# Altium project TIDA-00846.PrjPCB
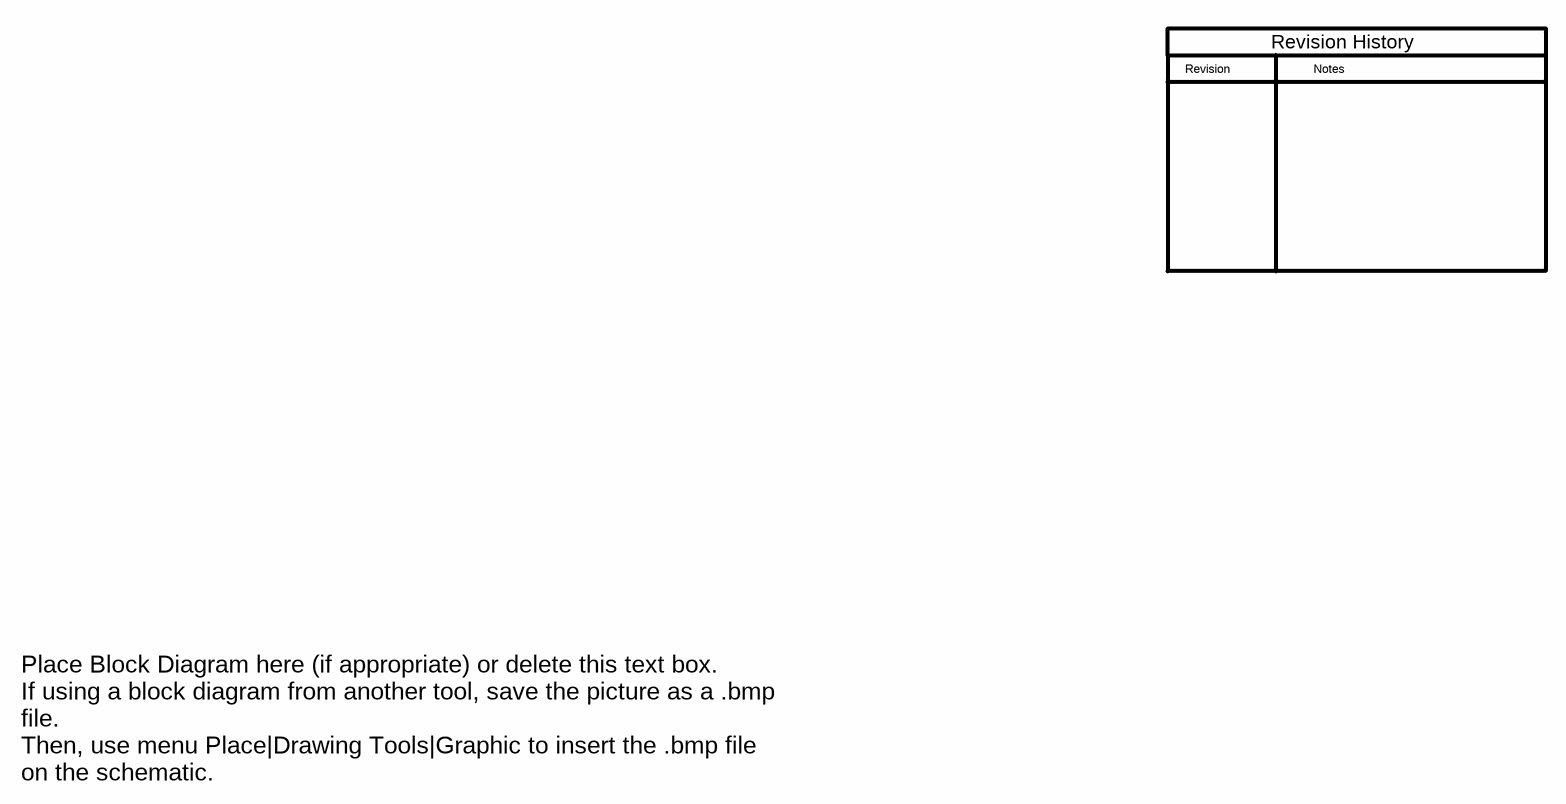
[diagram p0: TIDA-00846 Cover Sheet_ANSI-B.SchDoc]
CopyrightYear: 2015; PCB_Layout: Anda Zhang; PCB_Rev: E1; PRJ_Customer: Public Release; PRJ_Engineer: Anda Zhang; PRJ_Number: 001; PRJ_Title: TIDA-00846; SCH_Rev: E1; TechSupport: http://www.ti.com/support
3 sheets, 89 parts. Net scope: global (net labels, ports and power ports of the same name join across sheets).
Board file: TIDA-00846.PcbDoc
Sheets:
  TIDA-00846 Cover Sheet_ANSI-B.SchDoc
  TIDA-00846.SchDoc
  TIDA-00846_Hardware_ANSI-B.SchDoc

## Sheet TIDA-00846 Cover Sheet_ANSI-B.SchDoc
size 431 x 279 mm; Date: Not shown in title block; ApprovedBy: Not shown in title block; CheckedBy: Not shown in title block; Author: Not shown in title block; CompanyName: Not shown in title block; Engineer: Not shown in title block; Organization: Not shown in title block; Address1: Not shown in title block; Address2: Not shown in title block; Address3: Not shown in title block; Address4: Not shown in title block; DocumentNumber: 1; Revision: Use project parameter SCH_Rev; SheetNumber: 1; SheetTotal: 1; PageSetup: Record=PageOptions|CenterHorizontal=True|CenterVertical=True|PrintScale=1.00|XCorrection=1.00|YCorrection=1.00|PrintKind=0|BorderSize=5000000|LeftOffset=0|BottomOffset=0|Orientation=2|PaperLength=1000|PaperWidth=1000|Scale=100|PaperSource=15|PrintQuality=600|MediaType=1|DitherType=10|PaperKind=Letter|PrintScaleMode=1

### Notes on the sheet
- Revision
- Notes
- Revision History
- Place Block Diagram here (if appropriate) or delete this text box.
  If using a block diagram from another tool, save the picture as a .bmp file.
  Then, use menu Place|Drawing Tools|Graphic to insert the .bmp file on the schematic.

## Sheet TIDA-00846.SchDoc
size 558 x 431 mm; Date: Not shown in title block; ApprovedBy: Not shown in title block; CheckedBy: Not shown in title block; Author: Not shown in title block; CompanyName: Not shown in title block; Engineer: Not shown in title block; Organization: Not shown in title block; Address1: Not shown in title block; Address2: Not shown in title block; Address3: Not shown in title block; Address4: Not shown in title block; DocumentNumber: 1; Revision: Use project parameter SCH_Rev; SheetNumber: 1; SheetTotal: 1; PageSetup: Record=PageOptions¦CenterHorizontal=True¦CenterVertical=True¦PrintScale=1.00¦XCorrection=1.00¦YCorrection=1.00¦PrintKind=0¦BorderSize=5000000¦LeftOffset=0¦BottomOffset=0¦Orientation=2¦PaperLength=1000¦PaperWidth=1000¦Scale=100¦PaperSource=15¦PrintQuality=600¦MediaType=1¦DitherType=10¦PaperKind=Letter¦PrintScaleMode=1
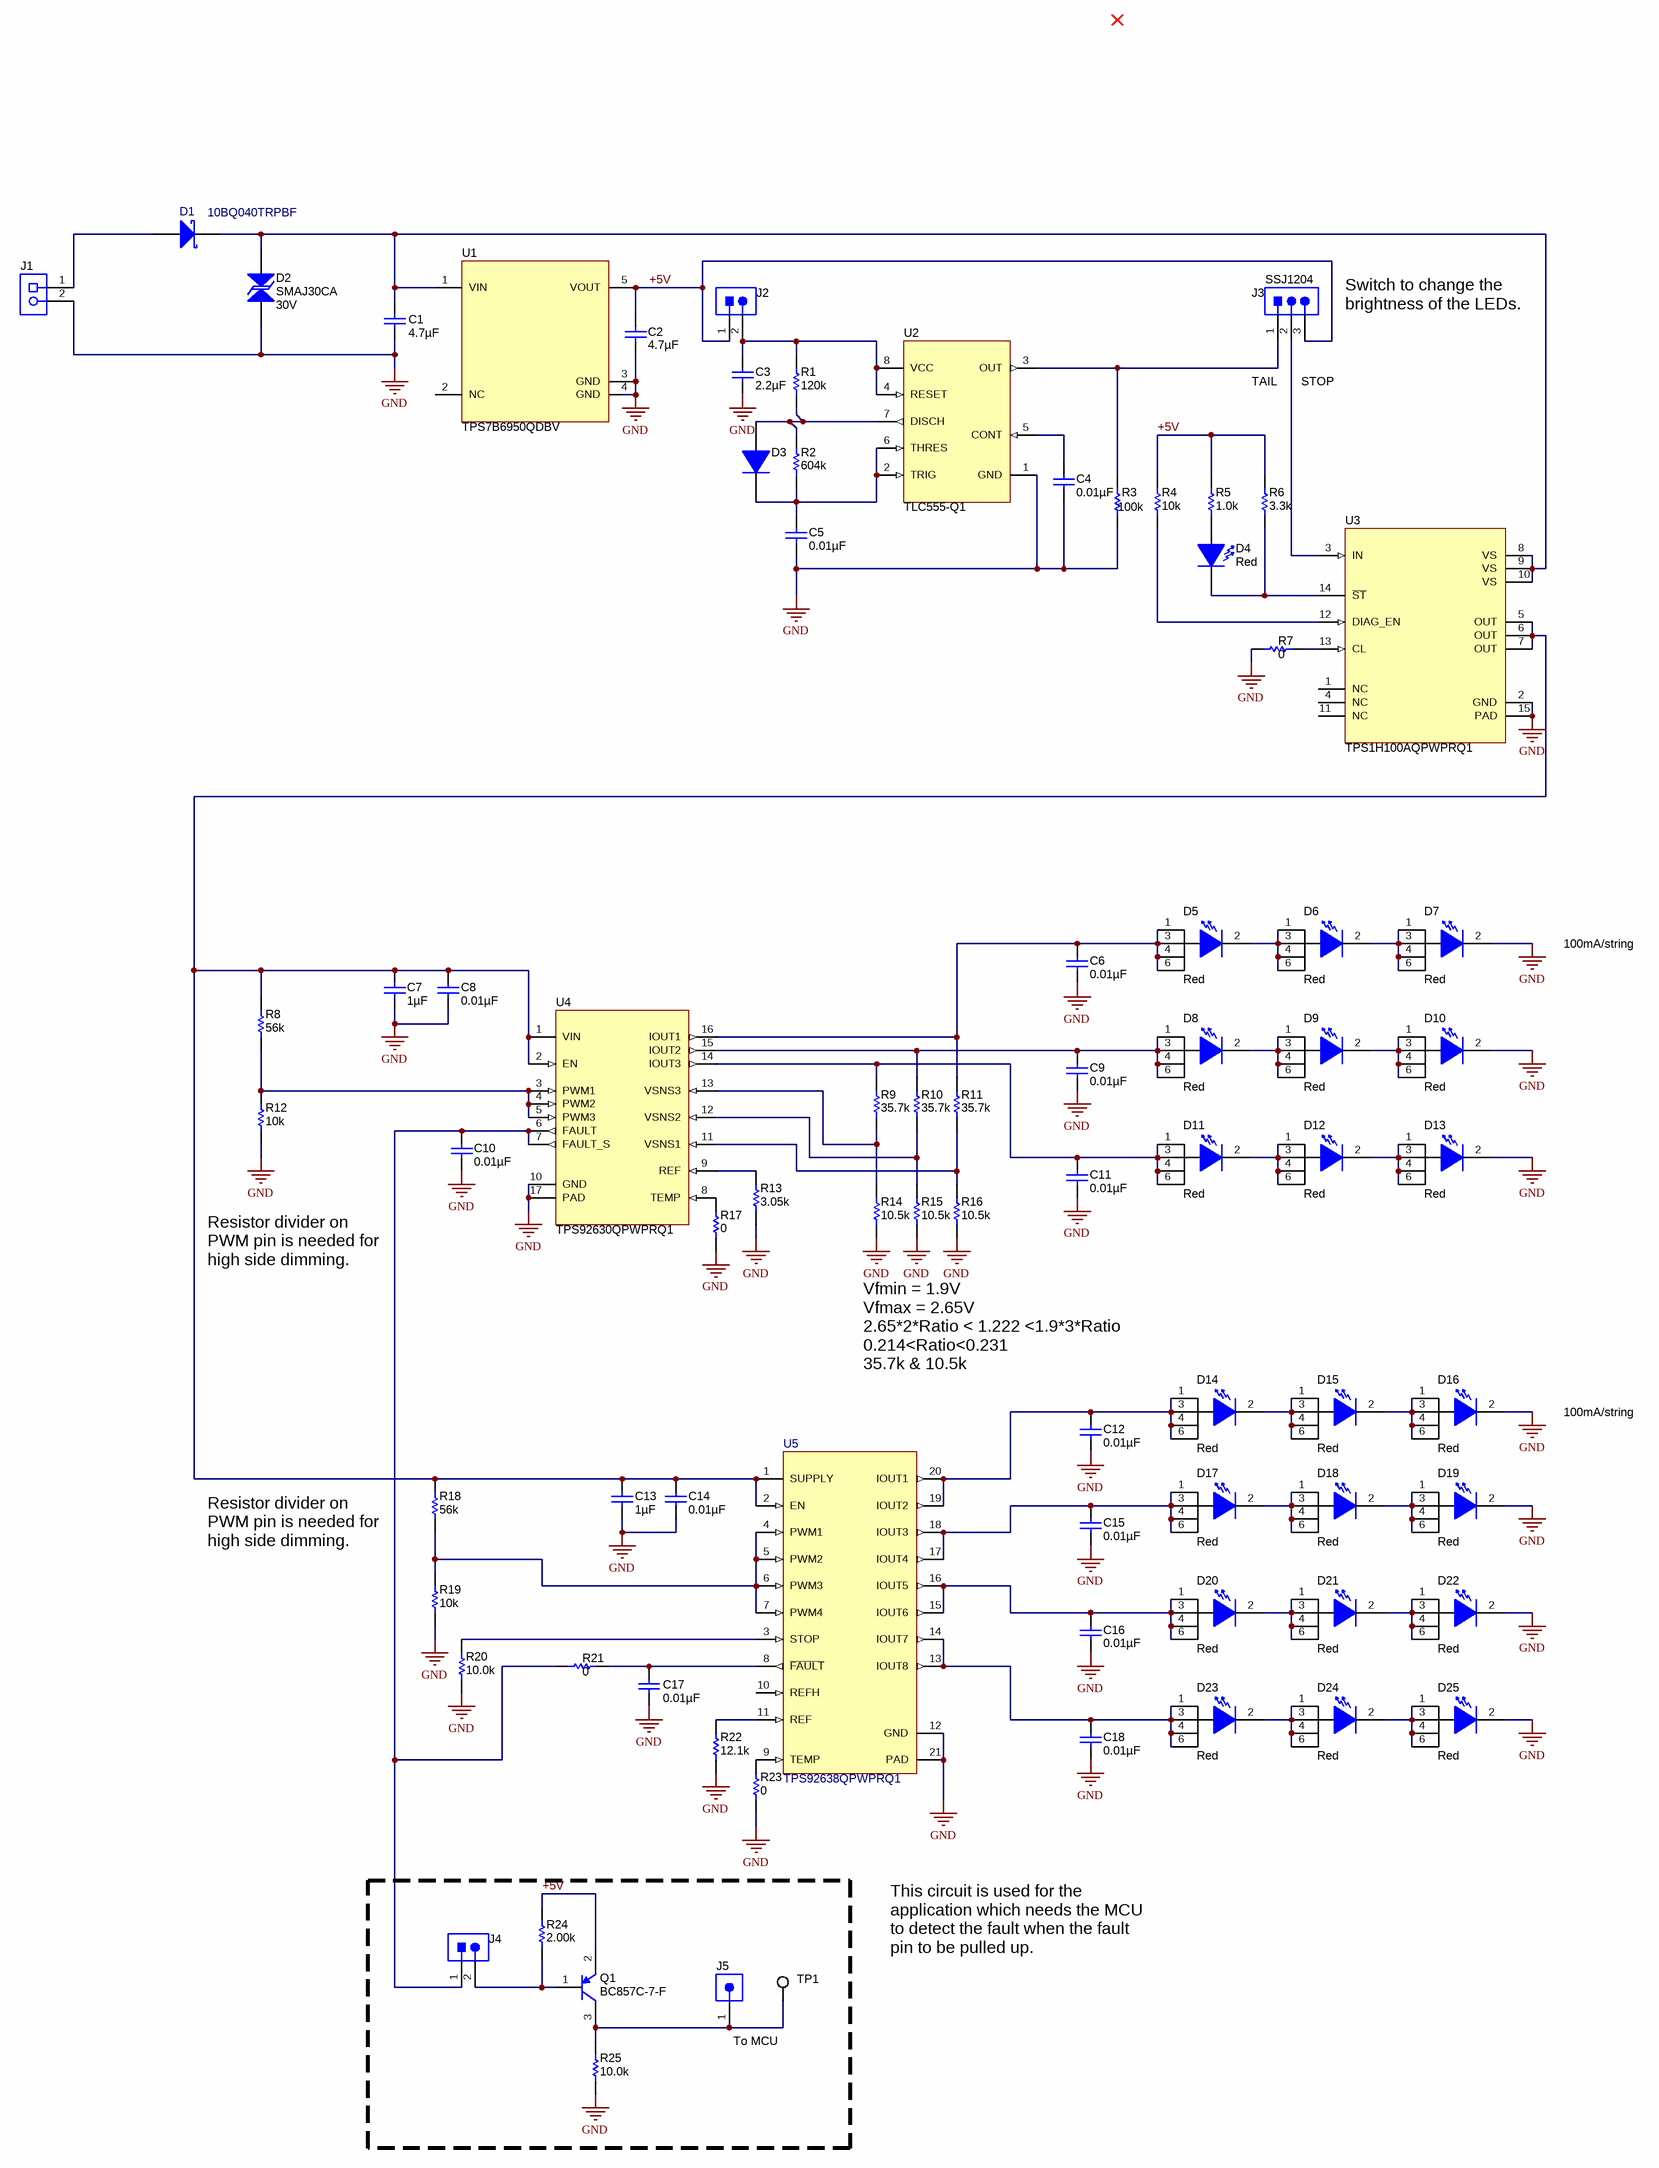
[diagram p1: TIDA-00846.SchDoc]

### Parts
C1  ValueDisplayed: 4.7µF  [0805L]  (hidden comment: C2012X5R1H475K125AB)
C2  ValueDisplayed: 4.7µF  [0603L]  (hidden comment: CGB3B1X5R1A475K055AC)
C3  ValueDisplayed: 2.2µF  [0603L]  (hidden comment: C0603C225K8PACTU)
C4  ValueDisplayed: 0.01µF  [0603L]  (hidden comment: 0603ZC103KAT2A)
C5  ValueDisplayed: 0.01µF  [0603L]  (hidden comment: 06031C103JAT2A)
C6  ValueDisplayed: 0.01µF  [0603L]  (hidden comment: 06031C103JAT2A)
C7  ValueDisplayed: 1µF  [0805L]  (hidden comment: C2012X7R1H105K125AB)
C8  ValueDisplayed: 0.01µF  [0603L]  (hidden comment: 06031C103JAT2A)
C9  ValueDisplayed: 0.01µF  [0603L]  (hidden comment: 06031C103JAT2A)
C10  ValueDisplayed: 0.01µF  [0603L]  (hidden comment: 06031C103JAT2A)
C11  ValueDisplayed: 0.01µF  [0603L]  (hidden comment: 06031C103JAT2A)
C12  ValueDisplayed: 0.01µF  [0603L]  (hidden comment: 06031C103JAT2A)
C13  ValueDisplayed: 1µF  [0805L]  (hidden comment: C2012X7R1H105K125AB)
C14  ValueDisplayed: 0.01µF  [0603L]  (hidden comment: 06031C103JAT2A)
C15  ValueDisplayed: 0.01µF  [0603L]  (hidden comment: 06031C103JAT2A)
C16  ValueDisplayed: 0.01µF  [0603L]  (hidden comment: 06031C103JAT2A)
C17  ValueDisplayed: 0.01µF  [0603L]  (hidden comment: 06031C103JAT2A)
C18  ValueDisplayed: 0.01µF  [0603L]  (hidden comment: 06031C103JAT2A)
D1  10BQ040TRPBF  [SMB]
D2  SMAJ30CA  value 30V  [SMA]
D3  1N4148W-7-F  [SOD-123]  (value not drawn)
D4  value Red  [LED_LTST-C170]  (hidden comment: LTST-C170KRKT)
D5  value Red  [LED_LR_G6SP]  (hidden comment: LR G6SP-CBEA-1-1)
D6  value Red  [LED_LR_G6SP]  (hidden comment: LR G6SP-CBEA-1-1)
D7  value Red  [LED_LR_G6SP]  (hidden comment: LR G6SP-CBEA-1-1)
D8  value Red  [LED_LR_G6SP]  (hidden comment: LR G6SP-CBEA-1-1)
D9  value Red  [LED_LR_G6SP]  (hidden comment: LR G6SP-CBEA-1-1)
D10  value Red  [LED_LR_G6SP]  (hidden comment: LR G6SP-CBEA-1-1)
D11  value Red  [LED_LR_G6SP]  (hidden comment: LR G6SP-CBEA-1-1)
D12  value Red  [LED_LR_G6SP]  (hidden comment: LR G6SP-CBEA-1-1)
D13  value Red  [LED_LR_G6SP]  (hidden comment: LR G6SP-CBEA-1-1)
D14  value Red  [LED_LR_G6SP]  (hidden comment: LR G6SP-CBEA-1-1)
D15  value Red  [LED_LR_G6SP]  (hidden comment: LR G6SP-CBEA-1-1)
D16  value Red  [LED_LR_G6SP]  (hidden comment: LR G6SP-CBEA-1-1)
D17  value Red  [LED_LR_G6SP]  (hidden comment: LR G6SP-CBEA-1-1)
D18  value Red  [LED_LR_G6SP]  (hidden comment: LR G6SP-CBEA-1-1)
D19  value Red  [LED_LR_G6SP]  (hidden comment: LR G6SP-CBEA-1-1)
D20  value Red  [LED_LR_G6SP]  (hidden comment: LR G6SP-CBEA-1-1)
D21  value Red  [LED_LR_G6SP]  (hidden comment: LR G6SP-CBEA-1-1)
D22  value Red  [LED_LR_G6SP]  (hidden comment: LR G6SP-CBEA-1-1)
D23  value Red  [LED_LR_G6SP]  (hidden comment: LR G6SP-CBEA-1-1)
D24  value Red  [LED_LR_G6SP]  (hidden comment: LR G6SP-CBEA-1-1)
D25  value Red  [LED_LR_G6SP]  (hidden comment: LR G6SP-CBEA-1-1)
J1  OSTTC022162  [On-Shore_OSTTC022162]  (value not drawn)
J2  HMTSW-102-07-G-S-240  [SAMTEC_HMTSW-102-07-G-S-240]  (value not drawn)
J3  value SSJ1204  [CONN_TMM-103-01-T-S]  (hidden comment: TMM-103-01-T-S)
J4  HMTSW-102-07-G-S-240  [SAMTEC_HMTSW-102-07-G-S-240]  (value not drawn)
J5  TSW-101-07-G-S  [TSW-101-07-G-S]  (value not drawn)
Q1  BC857C-7-F  [SOT-23]
R1  ValueDisplayed: 120k  [0603L]  (hidden comment: CRCW0603120KJNEA)
R2  ValueDisplayed: 604k  [0603]  (hidden comment: CRCW0603604KFKEA)
R3  ValueDisplayed: 100k  [0603L]  (hidden comment: CRCW0603100KFKEA)
R4  ValueDisplayed: 10k  [0603L]  (hidden comment: CRCW060310K0JNEA)
R5  ValueDisplayed: 1.0k  [0603L]  (hidden comment: CRCW06031K00JNEA)
R6  ValueDisplayed: 3.3k  [0603L]  (hidden comment: CRCW06033K30JNEA)
R7  ValueDisplayed: 0  [0603L]  (hidden comment: RC0603JR-070RL)
R8  ValueDisplayed: 56k  [0603L]  (hidden comment: CRCW060356K0JNEA)
R9  ValueDisplayed: 35.7k  [0603L]  (hidden comment: CRCW060335K7FKEA)
R10  ValueDisplayed: 35.7k  [0603L]  (hidden comment: CRCW060335K7FKEA)
R11  ValueDisplayed: 35.7k  [0603L]  (hidden comment: CRCW060335K7FKEA)
R12  ValueDisplayed: 10k  [0603L]  (hidden comment: CRCW060310K0JNEA)
R13  ValueDisplayed: 3.05k  [0603L]  (hidden comment: RT0603BRD073K05L)
R14  ValueDisplayed: 10.5k  [0603L]  (hidden comment: CRCW060310K5FKEA)
R15  ValueDisplayed: 10.5k  [0603L]  (hidden comment: CRCW060310K5FKEA)
R16  ValueDisplayed: 10.5k  [0603L]  (hidden comment: CRCW060310K5FKEA)
R17  ValueDisplayed: 0  [0603L]  (hidden comment: RC0603JR-070RL)
R18  ValueDisplayed: 56k  [0603L]  (hidden comment: CRCW060356K0JNEA)
R19  ValueDisplayed: 10k  [0603L]  (hidden comment: CRCW060310K0JNEA)
R20  ValueDisplayed: 10.0k  [0603L]  (hidden comment: CRCW060310K0FKEA)
R21  ValueDisplayed: 0  [0603L]  (hidden comment: RC0603JR-070RL)
R22  ValueDisplayed: 12.1k  [0603]  (hidden comment: RT0603DRE0712K1L)
R23  ValueDisplayed: 0  [0603L]  (hidden comment: RC0603JR-070RL)
R24  ValueDisplayed: 2.00k  [0603L]  (hidden comment: CRCW06032K00FKEA)
R25  ValueDisplayed: 10.0k  [0603L]  (hidden comment: CRCW060310K0FKEA)
TP1  5002  [Keystone5002]  (value not drawn)
U1  TPS7B6950QDBV  [DBV0005A_N]
U2  TLC555-Q1  [D0008A_L]
U3  TPS1H100AQPWPRQ1  [PWP0014C_N]
U4  TPS92630QPWPRQ1  [PWP0016F_N]
U5  TPS92638QPWPRQ1  [PWP0020B_N]

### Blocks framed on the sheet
To MCU: J4 J5 Q1 R24 R25 TP1

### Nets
GND: C1.2 C2.2 C3.2 C4.2 C5.2 C6.2 C7.2 C8.2 C9.2 C10.2 C11.2 C12.2 C13.2 C14.2 C15.2 C16.2 C17.2 C18.2 D2.1 D7.2(K) D10.2(K) D13.2(K) D16.2(K) D19.2(K) D22.2(K) D25.2(K) J1.2 R3.1 R7.2 R12.1 R13.1 R14.1 R15.1 R16.1 R17.1 R19.1 R20.1 R22.1 R23.1 R25.1 U1.3(GND) U1.4(GND) U2.1(GND) U3.2(GND) U3.15(PAD) U4.10(GND) U4.17(PAD) U5.12(GND) U5.21(PAD)
+5V: C2.1 J2.1 J3.3 Q1.2(E) R4.2 R5.2 R6.2 R24.2 U1.5(VOUT)
NetC1_1: C1.1 D1.1(K) D2.2 U1.1(VIN) U3.8(VS) U3.9(VS) U3.10(VS)
NetC3_1: C3.1 J2.2 R1.2 U2.4(RESET) U2.8(VCC)
NetC4_1: C4.1 U2.5(CONT)
NetC5_1: C5.1 D3.1(K) R2.1 U2.2(TRIG) U2.6(THRES)
NetC6_1: C6.1 D5.1(A) D5.3(A) D5.4(A) D5.6(A) R11.2 U4.16(IOUT1)
NetC7_1: C7.1 C8.1 C13.1 C14.1 R8.2 R18.2 U3.5(OUT) U3.6(OUT) U3.7(OUT) U4.1(VIN) U4.2(EN) U5.1(SUPPLY) U5.2(EN)
NetC9_1: C9.1 D8.1(A) D8.3(A) D8.4(A) D8.6(A) R10.2 U4.15(IOUT2)
NetC10_1: C10.1 J4.1 R21.2 U4.6(FAULT) U4.7(FAULT_S)
NetC11_1: C11.1 D11.1(A) D11.3(A) D11.4(A) D11.6(A) R9.2 U4.14(IOUT3)
NetC12_1: C12.1 D14.1(A) D14.3(A) D14.4(A) D14.6(A) U5.19(IOUT2) U5.20(IOUT1)
NetC15_1: C15.1 D17.1(A) D17.3(A) D17.4(A) D17.6(A) U5.17(IOUT4) U5.18(IOUT3)
NetC16_1: C16.1 D20.1(A) D20.3(A) D20.4(A) D20.6(A) U5.15(IOUT6) U5.16(IOUT5)
NetC17_1: C17.1 R21.1 U5.8(~{FAULT})
NetC18_1: C18.1 D23.1(A) D23.3(A) D23.4(A) D23.6(A) U5.13(IOUT8) U5.14(IOUT7)
NetD1_2: D1.2(A) J1.1
NetD3_2: D3.2(A) R1.1 R2.2 U2.7(DISCH)
NetD4_1: D4.1(A) R5.1
NetD4_2: D4.2(K) R6.1 U3.14(~{ST})
NetD5_2: D5.2(K) D6.1(A) D6.3(A) D6.4(A) D6.6(A)
NetD6_2: D6.2(K) D7.1(A) D7.3(A) D7.4(A) D7.6(A)
NetD8_2: D8.2(K) D9.1(A) D9.3(A) D9.4(A) D9.6(A)
NetD9_2: D9.2(K) D10.1(A) D10.3(A) D10.4(A) D10.6(A)
NetD11_2: D11.2(K) D12.1(A) D12.3(A) D12.4(A) D12.6(A)
NetD12_2: D12.2(K) D13.1(A) D13.3(A) D13.4(A) D13.6(A)
NetD14_2: D14.2(K) D15.1(A) D15.3(A) D15.4(A) D15.6(A)
NetD15_2: D15.2(K) D16.1(A) D16.3(A) D16.4(A) D16.6(A)
NetD17_2: D17.2(K) D18.1(A) D18.3(A) D18.4(A) D18.6(A)
NetD18_2: D18.2(K) D19.1(A) D19.3(A) D19.4(A) D19.6(A)
NetD20_2: D20.2(K) D21.1(A) D21.3(A) D21.4(A) D21.6(A)
NetD21_2: D21.2(K) D22.1(A) D22.3(A) D22.4(A) D22.6(A)
NetD23_2: D23.2(K) D24.1(A) D24.3(A) D24.4(A) D24.6(A)
NetD24_2: D24.2(K) D25.1(A) D25.3(A) D25.4(A) D25.6(A)
NetJ3_1: J3.1 R3.2 U2.3(OUT)
NetJ3_2: J3.2 U3.3(IN)
NetJ4_2: J4.2 Q1.1(B) R24.1
NetJ5_1: J5.1 Q1.3(C) R25.2 TP1.1
NetR4_1: R4.1 U3.12(DIAG_EN)
NetR7_1: R7.1 U3.13(CL)
NetR8_1: R8.1 R12.2 U4.3(PWM1) U4.4(PWM2) U4.5(PWM3)
NetR9_1: R9.1 R14.2 U4.13(VSNS3)
NetR10_1: R10.1 R15.2 U4.12(VSNS2)
NetR11_1: R11.1 R16.2 U4.11(VSNS1)
NetR13_2: R13.2 U4.9(REF)
NetR17_2: R17.2 U4.8(TEMP)
NetR18_1: R18.1 R19.2 U5.4(PWM1) U5.5(PWM2) U5.6(PWM3) U5.7(PWM4)
NetR20_2: R20.2 U5.3(STOP)
NetR22_2: R22.2 U5.11(REF)
NetR23_2: R23.2 U5.9(TEMP)

Not connected (* = marked no-connect by the designer): U1 2(NC); U3 1(NC) 4(NC) 11(NC); U5 10(REFH)

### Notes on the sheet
- (near J3) Switch to change the brightness of the LEDs.
- TAIL
- STOP
- 100mA/string
- Resistor divider on PWM pin is needed for high side dimming.
- Vfmin = 1.9V
  Vfmax = 2.65V
  2.65*2*Ratio < 1.222 <1.9*3*Ratio
  0.214<Ratio<0.231
  35.7k & 10.5k
- This circuit is used for the application which needs the MCU to detect the fault when the fault pin to be pulled up.

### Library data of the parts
C1 = C2012X5R1H475K125AB: CAP, CERM, 4.7 µF, 50 V, +/- 10%, X5R, 0805; Manufacturer: TDK; Polarized: N; CompType: Capacitor; Value: 4.7uF; U/M: EA; Cap_F: 0.0000047; Tolerance_%: 10; Value1: Unknown; VDC_V: 50; Value2: 50V; TaMin_C: -55; TaMax_C: 85; Cap_Case: 0805
C2 = CGB3B1X5R1A475K055AC: CAP, CERM, 4.7 µF, 10 V, +/- 10%, X5R, 0603; Manufacturer: TDK; Polarized: N; CompType: Capacitor; Value: 4.7uF; U/M: EA; Cap_F: 0.0000047; Tolerance_%: 10; Value1: Unknown; Value2: 10V; TaMin_C: -55; TaMax_C: 85; Cap_Case: 0603
C3 = C0603C225K8PACTU: CAP, CERM, 2.2 µF, 10 V, +/- 10%, X5R, 0603; Manufacturer: Kemet; Polarized: N; CompType: Capacitor; Value: 2.2uF; U/M: EA; Cap_F: 0.0000022; Tolerance_%: 10; Value1: Unknown; Value2: 10V; TaMin_C: -55; TaMax_C: 85; Cap_Case: 0603
C4 = 0603ZC103KAT2A: CAP, CERM, 0.01 µF, 10 V, +/- 10%, X7R, 0603; Manufacturer: AVX; Polarized: N; CompType: Capacitor; Value: 0.01uF; U/M: EA; Cap_F: 0.00000001; Tolerance_%: 10; Value1: Unknown; Value2: 10V; TaMin_C: -55; TaMax_C: 125; Cap_Case: 0603
C5 C6 C8-C12 C14-C18 = 06031C103JAT2A: CAP, CERM, 0.01uF, 100V, +/-5%, X7R, 0603; Manufacturer: AVX; Polarized: N; CompType: Capacitor; U/M: EA; Cap_F: 0.00000001; Tolerance_%: 5; ESR_Ohm: 0.098; Value1: 0.098 ohm; VDC_V: 100; TaMin_C: -55; TaMax_C: 125; Cap_Case: 0603
C7 C13 = C2012X7R1H105K125AB: CAP, CERM, 1 µF, 50 V, +/- 10%, X7R, 0805; Manufacturer: TDK; Polarized: N; CompType: Capacitor; Value: 1uF; U/M: EA; Cap_F: 0.000001; Tolerance_%: 10; Value1: Unknown; VDC_V: 50; Value2: 50V; TaMin_C: -55; TaMax_C: 125; Cap_Case: 0805
D1 = 10BQ040TRPBF: Diode, Schottky, 40V, 1A, SMB; Manufacturer: International Rectifier; U/M: EA; Vf_V: 0.53; Value2: 0.53V; Io_A: 1; Vr_V: 40; TJmax_C: 150; RJC_CperW: 36
D2 = SMAJ30CA: Diode, TVS, Bi, 30 V, 400 W, SMA; Manufacturer: Littelfuse; U/M: EA; Power_W: 400; Vr_V: 30; Value1: 400W; RJA_CperW: 120
D3 = 1N4148W-7-F: Diode, Ultrafast, 100 V, 0.15 A, SOD-123; Manufacturer: Diodes Inc.; U/M: EA; Vf_V: 1.25; Value: 100V; Value1: 0.15A; Value2: 1.25V; Io_A: 0.15; Vr_V: 100; TJmax_C: 150
D4 = LTST-C170KRKT: LED, Red, SMD; Manufacturer: Lite-On; Type: AlInGaP; Vf_V: 2; Value2: 2V; Io_A: 0.02; Value1: W; U/M: EA
D5-D25 = LR G6SP-CBEA-1-1: LED, Red, SMD; Manufacturer: OSRAM; SymbolCreator: a0411947; Vf_V: 2.1; Value2: 2.1V; Io_A: 0.14; RJC_CperW: 110; Tjmax_C: 150; Value1: W; U/M: EA
J1 = OSTTC022162: Terminal Block, 2-pole, 200mil, TH; Manufacturer: On-Shore Technology; SymbolCreator: a0412235; U/M: EA
J2 J4 = HMTSW-102-07-G-S-240: Header, 100mil, 2x1, Gold, TH; Manufacturer: Samtec; SymbolCreator: a0412235; U/M: EA
J3 = TMM-103-01-T-S: Header, 2mm, 3x1, Tin, TH; Manufacturer: Samtec; SymbolCreator: a0799628; U/M: EA
J5 = TSW-101-07-G-S: Header, 100mil, 1pos, Gold, TH; Manufacturer: Samtec; SymbolCreator: a0412235; U/M: EA
Q1 = BC857C-7-F, Diodes Inc.: Transistor, PNP, 45 V, 0.1 A, SOT-23; CompType: BJT; PNP: 1; NPN: 0; Vceo_V: 45; Vcesat1_V: 0.075; Value: 45 V; IcRated_A: 0.1; Value1: 0.1 A; HfeMax: 600; TaMin_C: -65; TaMax_C: 150; U/M: EA
R1 = CRCW0603120KJNEA: RES, 120 k, 5%, 0.1 W, 0603; Manufacturer: Vishay-Dale; CompType: Resistor; Value: 120k; Res_ohm: 120000; Tolerance_%: 5; Power_W: 0.1; Value2: 0.1W; VDC_V: 75; TempCo: 200 ppm/C; EIA_Code: E24; U/M: EA
R2 = CRCW0603604KFKEA: RES, 604 k, 1%, 0.1 W, 0603; Manufacturer: Vishay-Dale; CompType: Resistor; Value: 604k; Res_ohm: 604000; Tolerance_%: 1; Power_W: 0.1; Value2: 0.1W; VDC_V: 75; TempCo: 100 ppm/C; EIA_Code: E96; U/M: EA
R3 = CRCW0603100KFKEA: RES, 100 k, 1%, 0.1 W, 0603; Manufacturer: Vishay-Dale; CompType: Resistor; Value: 100k; Res_ohm: 100000; Tolerance_%: 1; Power_W: 0.1; Value2: 0.1W; VDC_V: 75; TempCo: 100 ppm/C; EIA_Code: E96; U/M: EA
R4 R12 R19 = CRCW060310K0JNEA: RES, 10 k, 5%, 0.1 W, 0603; Manufacturer: Vishay-Dale; CompType: Resistor; Value: 10k; Res_ohm: 10000; Value_Code: 10k0; Tolerance_%: 5; Power_W: 0.1; Value2: 0.1W; VDC_V: 75; TempCo: 200 ppm/C; EIA_Code: E24; U/M: EA
R5 = CRCW06031K00JNEA: RES, 1.0 k, 5%, 0.1 W, 0603; Manufacturer: Vishay-Dale; CompType: Resistor; Value: 1.0k; Res_ohm: 1000; Value_Code: 1k00; Tolerance_%: 5; Power_W: 0.1; Value2: 0.1W; VDC_V: 75; TempCo: 200 ppm/C; EIA_Code: E24; U/M: EA
R6 = CRCW06033K30JNEA: RES, 3.3 k, 5%, 0.1 W, 0603; Manufacturer: Vishay-Dale; CompType: Resistor; Value: 3.3k; Res_ohm: 3300; Value_Code: 3k30; Tolerance_%: 5; Power_W: 0.1; Value2: 0.1W; VDC_V: 75; TempCo: 200 ppm/C; EIA_Code: E24; U/M: EA
R7 R17 R21 R23 = RC0603JR-070RL: RES, 0, 5%, 0.1 W, 0603; Manufacturer: Yageo America; CompType: Resistor; Value: 0; Value_Code: 0000; Tolerance_%: 5; Power_W: 0.1; Value2: 0.1W; VDC_V: 50; TempCo: 200 ppm/C; EIA_Code: E24; U/M: EA
R8 R18 = CRCW060356K0JNEA: RES, 56 k, 5%, 0.1 W, 0603; Manufacturer: Vishay-Dale; CompType: Resistor; Value: 56k; Res_ohm: 56000; Value_Code: 56k0; Tolerance_%: 5; Power_W: 0.1; Value2: 0.1W; VDC_V: 75; TempCo: 200 ppm/C; EIA_Code: E24; U/M: EA
R9-R11 = CRCW060335K7FKEA: RES, 35.7 k, 1%, 0.1 W, 0603; Manufacturer: Vishay-Dale; CompType: Resistor; Value: 35.7k; Res_ohm: 35700; Value_Code: 35k7; Tolerance_%: 1; Power_W: 0.1; Value2: 0.1W; VDC_V: 75; TempCo: 100 ppm/C; EIA_Code: E96; U/M: EA
R13 = RT0603BRD073K05L: RES, 3.05 k, 0.1%, 0.1 W, 0603; Manufacturer: Yageo America; CompType: Resistor; Value: 3.05k; Res_ohm: 3050; Value_Code: 3k05; Tolerance_%: 0.1; Value2: 0.1W; VDC_V: 75; TempCo: 25 ppm/C; EIA_Code: E192; U/M: EA
R14-R16 = CRCW060310K5FKEA: RES, 10.5 k, 1%, 0.1 W, 0603; Manufacturer: Vishay-Dale; CompType: Resistor; Value: 10.5k; Res_ohm: 10500; Value_Code: 10k5; Tolerance_%: 1; Power_W: 0.1; Value2: 0.1W; VDC_V: 75; TempCo: 100 ppm/C; EIA_Code: E96; U/M: EA
R20 R25 = CRCW060310K0FKEA: RES, 10.0 k, 1%, 0.1 W, 0603; Manufacturer: Vishay-Dale; CompType: Resistor; Value: 10.0k; Res_ohm: 10000; Value_Code: 10k0; Tolerance_%: 1; Power_W: 0.1; Value2: 0.1W; VDC_V: 75; TempCo: 100 ppm/C; EIA_Code: E96; U/M: EA
R22 = RT0603DRE0712K1L: RES, 12.1 k, 0.5%, 0.1 W, 0603; Manufacturer: Yageo America; CompType: Resistor; Value: 12.1k; Res_ohm: 12100; Value_Code: 12k1; Tolerance_%: 0.5; Power_W: 0.1; Value2: 0.1W; VDC_V: 75; TempCo: 50 ppm/C; EIA_Code: E192; U/M: EA
R24 = CRCW06032K00FKEA: RES, 2.00 k, 1%, 0.1 W, 0603; Manufacturer: Vishay-Dale; CompType: Resistor; Value: 2.00k; Res_ohm: 2000; Value_Code: 2k00; Tolerance_%: 1; Power_W: 0.1; Value2: 0.1W; VDC_V: 75; TempCo: 100 ppm/C; EIA_Code: E96; U/M: EA
TP1 = 5002: Test Point, Miniature, White, TH; Manufacturer: Keystone; CompType: Test Point Loop; U/M: EA
U1 = TPS7B6950QDBV: High Voltage Ultra Low Iq - Low Drop Out Regulator, DBV0005A; Manufacturer: Texas Instruments; SymbolCreator: Altium; CompType: IC; U/M: EA
U2 = TLC555CD: LinCMOS Timer, D0008A; Manufacturer: Texas Instruments; SymbolCreator: a0799628; CompType: IC; U/M: EA
U3 = TPS1H100AQPWPRQ1: 40V/100mO Single Channel Smart High Side Switch, Automotive Qualified, PWP0014C; Manufacturer: Texas Instruments; SymbolCreator: a0411947; CompType: IC; U/M: EA
U4 = TPS92630QPWPRQ1: Three-Channel Linear LED Driver with Analog and PWM Dimming, PWP0016F; Manufacturer: Texas Instruments; SymbolCreator: a0411947; CompType: IC; U/M: EA
U5 = TPS92638QPWPRQ1: Eight-Channel Linear LED Driver with PWM Dimming, PWP0020B; Alternate Manufacturer: None; Manufacturer: Texas Instruments; SymbolCreator: a0411947; CompType: IC; U/M: EA

## Sheet TIDA-00846_Hardware_ANSI-B.SchDoc
size 431 x 279 mm; Date: Not shown in title block; ApprovedBy: Not shown in title block; CheckedBy: Not shown in title block; Author: Not shown in title block; CompanyName: Not shown in title block; Engineer: Not shown in title block; Organization: Not shown in title block; Address1: Not shown in title block; Address2: Not shown in title block; Address3: Not shown in title block; Address4: Not shown in title block; DocumentNumber: 1; Revision: Use project parameter SCH_Rev; SheetNumber: 1; SheetTotal: 1; PageSetup: Record=PageOptions¦CenterHorizontal=True¦CenterVertical=True¦PrintScale=1.00¦XCorrection=1.00¦YCorrection=1.00¦PrintKind=0¦BorderSize=5000000¦LeftOffset=0¦BottomOffset=0¦Orientation=2¦PaperLength=1000¦PaperWidth=1000¦Scale=100¦PaperSource=15¦PrintQuality=600¦MediaType=1¦DitherType=10¦PaperKind=Letter¦PrintScaleMode=1
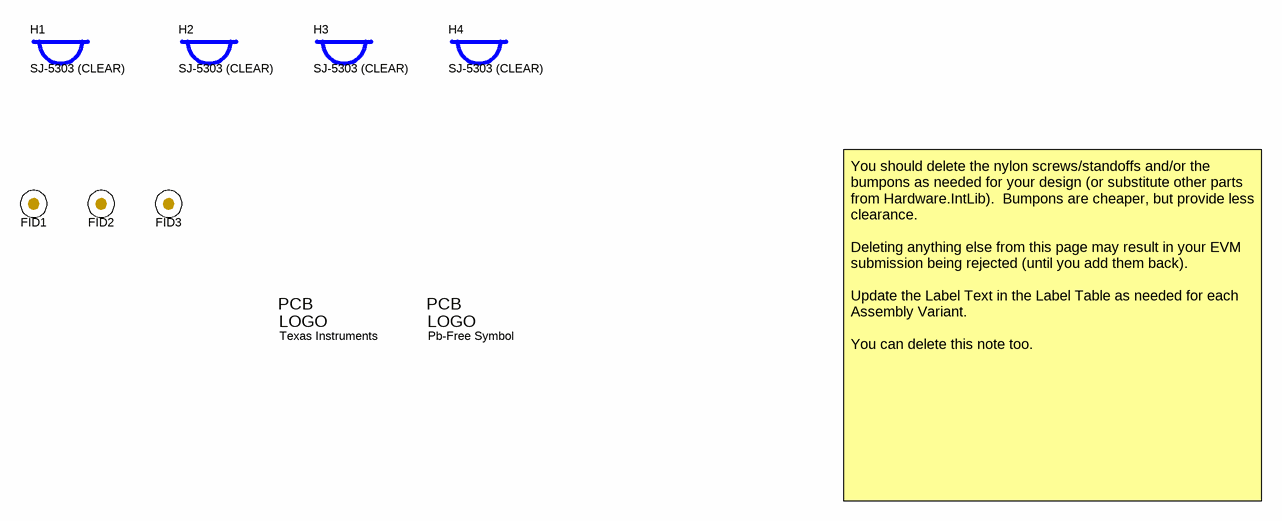
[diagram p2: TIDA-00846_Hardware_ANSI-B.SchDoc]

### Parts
FID1  Fiducial  [Fiducial10-20]  (value not drawn)
FID2  Fiducial  [Fiducial10-20]  (value not drawn)
FID3  Fiducial  [Fiducial10-20]  (value not drawn)
H1  SJ-5303 (CLEAR)  [Bumpon_SJ5003Transparent]
H2  SJ-5303 (CLEAR)  [Bumpon_SJ5003Transparent]
H3  SJ-5303 (CLEAR)  [Bumpon_SJ5003Transparent]
H4  SJ-5303 (CLEAR)  [Bumpon_SJ5003Transparent]
Logo1  Texas Instruments  [TI_Stacked_SolderMask_Small]  (no BOM)
Logo2  Pb-Free Symbol  [Pb-Free_Overlay_Small]  (no BOM)

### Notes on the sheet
- You should delete the nylon screws/standoffs and/or the bumpons as needed for your design (or substitute other parts from Hardware.IntLib).  Bumpons are cheaper, but provide less clearance.
  Deleting anything else from this page may result in your EVM submission being rejected (until you add them back).
  Update the Label Text in the Label Table as needed for each Assembly Variant.
  You can delete this note too.

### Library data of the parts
FID1-FID3 = Fiducial: Fiducial mark.  There is nothing to buy or mount.; SymbolCreator: codlsc
H1-H4 = SJ-5303 (CLEAR): Bumpon, Hemisphere, 0.44 X 0.20, Clear; Manufacturer: 3M; SymbolCreator: a0412235
Logo1 = TI_Logo: Texas Instrument Corporate Signature; SymbolCreator: a0412235
Logo2 = Pb-Free: SymbolCreator: a0412235

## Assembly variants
001: not fitted FID1 FID2 FID3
